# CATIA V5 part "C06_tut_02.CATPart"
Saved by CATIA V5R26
Part number: Part1
Bounding box of the stored display mesh (mm): x -75 to 75, y -125 to 125, z 0 to 28.103
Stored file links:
  D:\_Deepak\CATIA\CATIA V5 2015 Parts Files\Tutorial Files\Tutorials\c06_catia_v5_6r2015_tut\C06_tut_02.CATPart
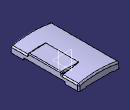
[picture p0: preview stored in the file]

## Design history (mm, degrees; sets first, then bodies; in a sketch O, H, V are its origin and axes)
Body1 (main body)
  Sketch1 on zx-plane, origin (0, 0, 0), H (-1, 0, 0), V (0, 0, 1)
    point P1 (-75, 0)
    line L1 (-75, 0) -> (75, 0)
    line L2 (75, 0) -> (75, 20)
    line L3 (-75, 20) -> (-75, 0)
    point P2 (75, 0)
    point P3 (75, 20)
    arc A1 centre (0, -321.8699) radius 350 from (75, 20) to (-75, 20) ccw
    point P6 (0, 28.1301)
    radius A1 = 350
    distance P3 P2 = 20
    distance V A1 = 350
    distance L3 L2 = 150
    coincidence: P1 H, A1 P6, P6 V
    horizontal: L1 H
    vertical: L2 V, L3 V
    symmetry: P2 P1 V
  Pad1: profile Sketch1, direction (0, 1, 0), length 125, mirrored extent
  Plane1: type Offset, RefPlane face of Pad1 from Sketch1.L1, Offset -28, reversed
  Sketch2 on Plane1, origin (0, 0, 28), H (1, 0, 0), V (0, 1, 0)
    line L1 (0, 62.5) -> (75, 62.5)
    line L2 (75, 62.5) -> (75, -62.5)
    line L3 (75, -62.5) -> (0, -62.5)
    line L4 (0, -62.5) -> (0, 62.5)
    reference projected line E1 (75, -125) -> (75, 125) from edge [face of Pad1 from Sketch1.L3 | face of Pad1 from Sketch1.A1]
    length L2 = 125
    distance H L1 = 62.5
    length L3 = 75
    horizontal: L1 H, L3 H
    vertical: L2 V, L4 V
    coincidence: L2 E1
  Pad2: profile Sketch2, direction (0, 0, 1), up to the existing solid (limit type 3)
  Draft1: Angle -3, Neutral face of Pad1 from Sketch1.L1, PullDir face of Pad1 from Sketch1.L1, SupportToDraft (end face of Pad1; face of Pad1; face of Pad1 from Sketch1.L2; start face of Pad1)
  Fillet1: radius 3, on edge [face of Pad2 from Sketch2.L3 | face of Pad2]; edge [face of Pad2 from Sketch2.L1 | face of Pad2]; edge [face of Pad1 | face of Pad2]
  Fillet2: radius 1, on edge [face of Pad1 from Sketch1.A1 | face of Pad2 from Sketch2.L1]
  Fillet3: radius 5, on edge [end face of Pad1 | face of Pad1 from Sketch1.A1]; edge [face of Pad1 from Sketch1.L2 | face of Pad1 from Sketch1.A1]; edge [start face of Pad1 | face of Pad1 from Sketch1.A1]; edge [face of Pad1 | face of Pad1 from Sketch1.A1] (x2); edge [face of Pad1 | end face of Pad1]; edge [start face of Pad1 | face of Pad1]; edge [start face of Pad1 | face of Pad1 from Sketch1.L2]; edge [face of Pad1 from Sketch1.L2 | end face of Pad1]
  Shell1: ExtOffset 0, Face face of Pad1 from Sketch1.L1, IntOffset 2
  Sketch3 on yz-plane, origin (0, 0, 0), H (0, 1, 0), V (0, 0, 1)
    line L1 (-75, 7) -> (75, 7)
    line L2 (75, 7) -> (75, -4.884)
    line L3 (75, -4.884) -> (-75, -4.884)
    line L4 (-75, -4.884) -> (-75, 7)
    point P3 (75, -4.884)
    point P4 (-75, -4.884)
    length L2 = 11.884
    distance H L1 = 7
    length L3 = 150
    horizontal: L1 H, L3 H
    vertical: L2 V, L4 V
    symmetry: P4 P3 V
  Pocket1: profile Sketch3, direction (-1, 0, 0), length 125, mirrored extent
  Sketch4 on zx-plane, origin (0, 0, 0), H (-1, 0, 0), V (0, 0, 1)
    line L1 (-50, 3) -> (50, 3)
    line L2 (50, 3) -> (50, -5.0414)
    line L3 (50, -5.0414) -> (-50, -5.0414)
    line L4 (-50, -5.0414) -> (-50, 3)
    reference projected line E1 (75, 0) -> (-75, 0) from edge [end face of Pad1 | face of Pad1 from Sketch1.L1]
    distance L2 L4 = 100
    distance V L2 = 50
    distance L1 E1 = 3
    horizontal: L1 H, L3 H
    vertical: L2 V, L4 V
  Pocket2: profile Sketch4, direction (0, -1, 0), length 133, mirrored extent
